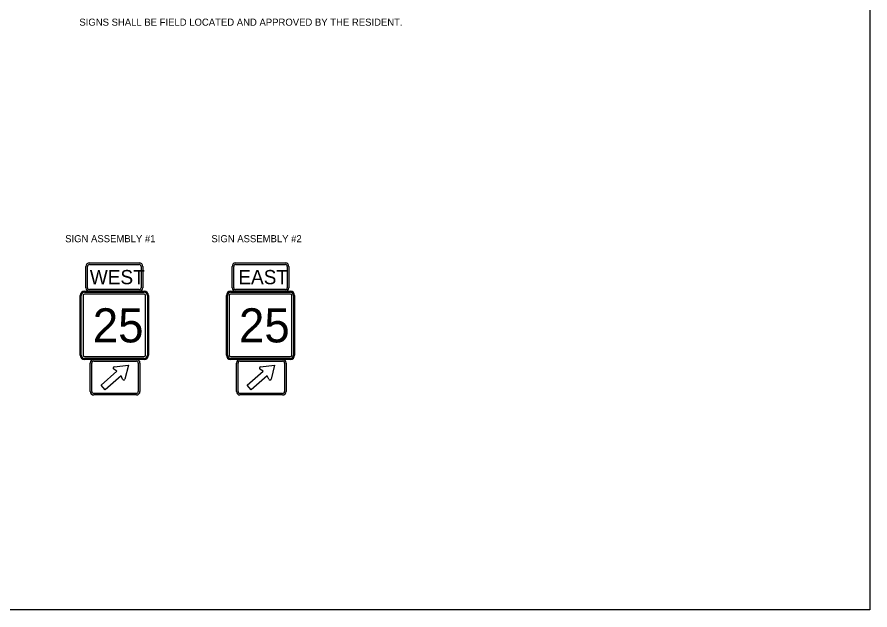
# Model space of a CAD drawing. Extents: x 914742 to 915492, y 328736 to 329423.
# Drawn here: x 915116.7 to 915491.7, y 328898.3 to 329159.1 of the extents above; entities that cross this region are included whole.
import ezdxf

# ---------------------------------------------------------------- set-up
doc = ezdxf.new("R2010")
doc.units = 0
for name, color, linetype in [('ANNOTATION', 7, 'Continuous'), ('PLOT BOUNDARY', 7, 'Continuous'), ('SignPanel', 7, 'Continuous'), ('SIGNS TRAFFIC', 7, 'Continuous')]:
    doc.layers.add(name, color=color, linetype=linetype)

msp = doc.modelspace()

# ---------------------------------------------------------------- linework, layer by layer
at = {"layer": 'PLOT BOUNDARY'}
msp.add_lwpolyline([(915491.67, 328898.32), (914741.67, 328898.32), (914741.67, 329423.32), (915491.67, 329423.32)], close=True, dxfattribs=at)
msp.add_lwpolyline([(914741.67, 328925.96), (914741.67, 329423.32), (915491.67, 329423.32), (915491.67, 328925.96)], dxfattribs=at)
at = {"layer": 'SignPanel'}
for p, q in [((915153.59, 328997.23), (915160.59, 329003.38)), ((915160.59, 329003.38), (915159.17, 329004.27)), ((915159.39, 329005.23), (915165.62, 329005.97)), ((915165.62, 329005.97), (915164.07, 328999.88)), ((915217.87, 328997.23), (915224.87, 329003.38)), ((915224.87, 329003.38), (915223.45, 329004.27)), ((915223.67, 329005.23), (915229.9, 329005.97)), ((915229.9, 329005.97), (915228.35, 328999.88)), ((915162.4, 329001.32), (915155.39, 328995.17)), ((915163.1, 328999.79), (915162.4, 329001.32)), ((915226.68, 329001.32), (915219.67, 328995.17)), ((915227.38, 328999.79), (915226.68, 329001.32)), ((915155.39, 328995.17), (915153.59, 328997.23)), ((915219.67, 328995.17), (915217.87, 328997.23))]:
    msp.add_line(p, q, dxfattribs=at)
for points in [[(915146.92, 329040.07), (915146.92, 329049.44)], [(915147.64, 329040.07), (915147.64, 329049.44)], [(915148.49, 329051.01), (915170.36, 329051.01)], [(915148.49, 329050.29), (915170.36, 329050.29)], [(915171.21, 329049.44), (915171.21, 329040.07)], [(915171.92, 329049.44), (915171.92, 329040.07)], [(915211.21, 329040.07), (915211.21, 329049.44)], [(915211.92, 329040.07), (915211.92, 329049.44)], [(915212.77, 329051.01), (915234.65, 329051.01)], [(915212.77, 329050.29), (915234.65, 329050.29)], [(915235.49, 329049.44), (915235.49, 329040.07)], [(915236.21, 329049.44), (915236.21, 329040.07)], [(915170.36, 329039.22), (915148.49, 329039.22)], [(915170.36, 329038.51), (915148.49, 329038.51)], [(915234.65, 329039.22), (915212.77, 329039.22)], [(915234.65, 329038.51), (915212.77, 329038.51)], [(915148.82, 328994.44), (915148.82, 329006.94)], [(915149.54, 328994.44), (915149.54, 329006.94)], [(915150.39, 329008.51), (915169.14, 329008.51)], [(915150.39, 329007.79), (915169.14, 329007.79)], [(915169.98, 329006.94), (915169.98, 328994.44)], [(915170.7, 329006.94), (915170.7, 328994.44)], [(915213.1, 328994.44), (915213.1, 329006.94)], [(915213.82, 328994.44), (915213.82, 329006.94)], [(915214.67, 329008.51), (915233.42, 329008.51)], [(915214.67, 329007.79), (915233.42, 329007.79)], [(915234.26, 329006.94), (915234.26, 328994.44)], [(915234.98, 329006.94), (915234.98, 328994.44)], [(915169.14, 328993.6), (915150.39, 328993.6)], [(915169.14, 328992.88), (915150.39, 328992.88)], [(915233.42, 328993.6), (915214.67, 328993.6)], [(915233.42, 328992.88), (915214.67, 328992.88)]]:
    msp.add_lwpolyline(points, dxfattribs=at)
for centre, radius, start, end in [((915148.49, 329049.44), 1.56, 90, 180), ((915148.49, 329049.44), 0.846, 90, 180), ((915170.36, 329049.44), 1.56, 360, 90), ((915170.36, 329049.44), 0.846, 360, 90), ((915212.77, 329049.44), 1.56, 90, 180), ((915212.77, 329049.44), 0.846, 90, 180), ((915234.65, 329049.44), 1.56, 360, 90), ((915234.65, 329049.44), 0.846, 360, 90), ((915148.49, 329040.07), 1.56, 180, 270), ((915148.49, 329040.07), 0.846, 180, 270), ((915170.36, 329040.07), 1.56, 270, 0), ((915170.36, 329040.07), 0.846, 270, 0), ((915212.77, 329040.07), 1.56, 180, 270), ((915212.77, 329040.07), 0.846, 180, 270), ((915234.65, 329040.07), 1.56, 270, 0), ((915234.65, 329040.07), 0.846, 270, 0), ((915150.39, 329006.94), 1.56, 90, 180), ((915150.39, 329006.94), 0.846, 90, 180), ((915169.14, 329006.94), 1.56, 360, 90), ((915169.14, 329006.94), 0.846, 360, 90), ((915214.67, 329006.94), 1.56, 90, 180), ((915214.67, 329006.94), 0.846, 90, 180), ((915233.42, 329006.94), 1.56, 360, 90), ((915233.42, 329006.94), 0.846, 360, 90), ((915159.45, 329004.71), 0.521, 96.7689, 237.9013), ((915223.73, 329004.71), 0.521, 96.7689, 237.9013), ((915163.57, 329000.01), 0.521, 204.6127, 345.7451), ((915227.85, 329000.01), 0.521, 204.6127, 345.7451), ((915150.39, 328994.44), 1.56, 180, 270), ((915150.39, 328994.44), 0.846, 180, 270), ((915169.14, 328994.44), 1.56, 270, 0), ((915169.14, 328994.44), 0.846, 270, 0), ((915214.67, 328994.44), 1.56, 180, 270), ((915214.67, 328994.44), 0.846, 180, 270), ((915233.42, 328994.44), 1.56, 270, 0), ((915233.42, 328994.44), 0.846, 270, 0)]:
    msp.add_arc(centre, radius, start, end, dxfattribs=at)
at = {"layer": 'SIGNS TRAFFIC'}
for points in [[(915144.42, 329010.38), (915144.42, 329036.63)], [(915144.42, 329010.38), (915144.42, 329036.63)], [(915144.89, 329010.38), (915144.89, 329036.63)], [(915145.67, 329036.63), (915145.67, 329010.38)], [(915146.3, 329038.51), (915172.55, 329038.51)], [(915146.3, 329038.51), (915172.55, 329038.51)], [(915146.3, 329038.04), (915172.55, 329038.04)], [(915172.55, 329037.26), (915146.3, 329037.26)], [(915173.17, 329010.38), (915173.17, 329036.63)], [(915173.96, 329036.63), (915173.96, 329010.38)], [(915174.42, 329036.63), (915174.42, 329010.38)], [(915174.42, 329036.63), (915174.42, 329010.38)], [(915208.71, 329010.38), (915208.71, 329036.63)], [(915208.71, 329010.38), (915208.71, 329036.63)], [(915209.17, 329010.38), (915209.17, 329036.63)], [(915209.96, 329036.63), (915209.96, 329010.38)], [(915210.58, 329038.51), (915236.83, 329038.51)], [(915210.58, 329038.51), (915236.83, 329038.51)], [(915210.58, 329038.04), (915236.83, 329038.04)], [(915236.83, 329037.26), (915210.58, 329037.26)], [(915237.45, 329010.38), (915237.45, 329036.63)], [(915238.24, 329036.63), (915238.24, 329010.38)], [(915238.71, 329036.63), (915238.71, 329010.38)], [(915238.71, 329036.63), (915238.71, 329010.38)], [(915146.3, 329009.76), (915172.55, 329009.76)], [(915172.55, 329008.97), (915146.3, 329008.97)], [(915172.55, 329008.51), (915146.3, 329008.51)], [(915172.55, 329008.51), (915146.3, 329008.51)], [(915210.58, 329009.76), (915236.83, 329009.76)], [(915236.83, 329008.97), (915210.58, 329008.97)], [(915236.83, 329008.51), (915210.58, 329008.51)], [(915236.83, 329008.51), (915210.58, 329008.51)]]:
    msp.add_lwpolyline(points, dxfattribs=at)
for centre, radius, start, end in [((915146.3, 329036.63), 1.87, 90, 180), ((915146.3, 329036.63), 1.87, 90, 180), ((915146.3, 329036.63), 1.41, 90, 180), ((915146.3, 329036.63), 0.625, 90, 180), ((915172.55, 329036.63), 1.87, 0, 90), ((915172.55, 329036.63), 1.87, 0, 90), ((915172.55, 329036.63), 1.41, 0, 90), ((915172.55, 329036.63), 0.625, 0, 90), ((915210.58, 329036.63), 1.87, 90, 180), ((915210.58, 329036.63), 1.87, 90, 180), ((915210.58, 329036.63), 1.41, 90, 180), ((915210.58, 329036.63), 0.625, 90, 180), ((915236.83, 329036.63), 1.87, 0, 90), ((915236.83, 329036.63), 1.87, 0, 90), ((915236.83, 329036.63), 1.41, 0, 90), ((915236.83, 329036.63), 0.625, 0, 90), ((915146.3, 329010.38), 1.87, 180, 270), ((915146.3, 329010.38), 1.87, 180, 270), ((915146.3, 329010.38), 1.41, 180, 270), ((915146.3, 329010.38), 0.625, 180, 270), ((915172.55, 329010.38), 1.87, 270, 0), ((915172.55, 329010.38), 1.87, 270, 0), ((915172.55, 329010.38), 1.41, 270, 0), ((915172.55, 329010.38), 0.625, 270, 0), ((915210.58, 329010.38), 1.87, 180, 270), ((915210.58, 329010.38), 1.87, 180, 270), ((915210.58, 329010.38), 1.41, 180, 270), ((915210.58, 329010.38), 0.625, 180, 270), ((915236.83, 329010.38), 1.87, 270, 0), ((915236.83, 329010.38), 1.87, 270, 0), ((915236.83, 329010.38), 1.41, 270, 0), ((915236.83, 329010.38), 0.625, 270, 0)]:
    msp.add_arc(centre, radius, start, end, dxfattribs=at)

# ---------------------------------------------------------------- texts
at = {"layer": 'ANNOTATION'}
for s, p in [('SIGNS SHALL BE FIELD LOCATED AND APPROVED BY THE RESIDENT.', (915144.07, 329155.31)), ('SIGNS SHALL BE FIELD LOCATED AND APPROVED BY THE RESIDENT.', (915144.07, 329155.31)), ('SIGN ASSEMBLY #1', (915137.82, 329060.07)), ('SIGN ASSEMBLY #2', (915202.11, 329060.07))]:
    msp.add_text(s, height=3.125, dxfattribs=at).set_placement(p)
at = {"layer": 'SignPanel'}
for s, p in [('WEST', (915148.67, 329041.61)), ('EAST', (915213.96, 329041.61))]:
    msp.add_text(s, height=6.25, dxfattribs=at).set_placement(p)
at = {"layer": 'SIGNS TRAFFIC'}
for p in [(915149.96, 329016.01), (915214.24, 329016.01)]:
    msp.add_text('25', height=15, dxfattribs=at).set_placement(p)

doc.saveas('drawing.dxf')
